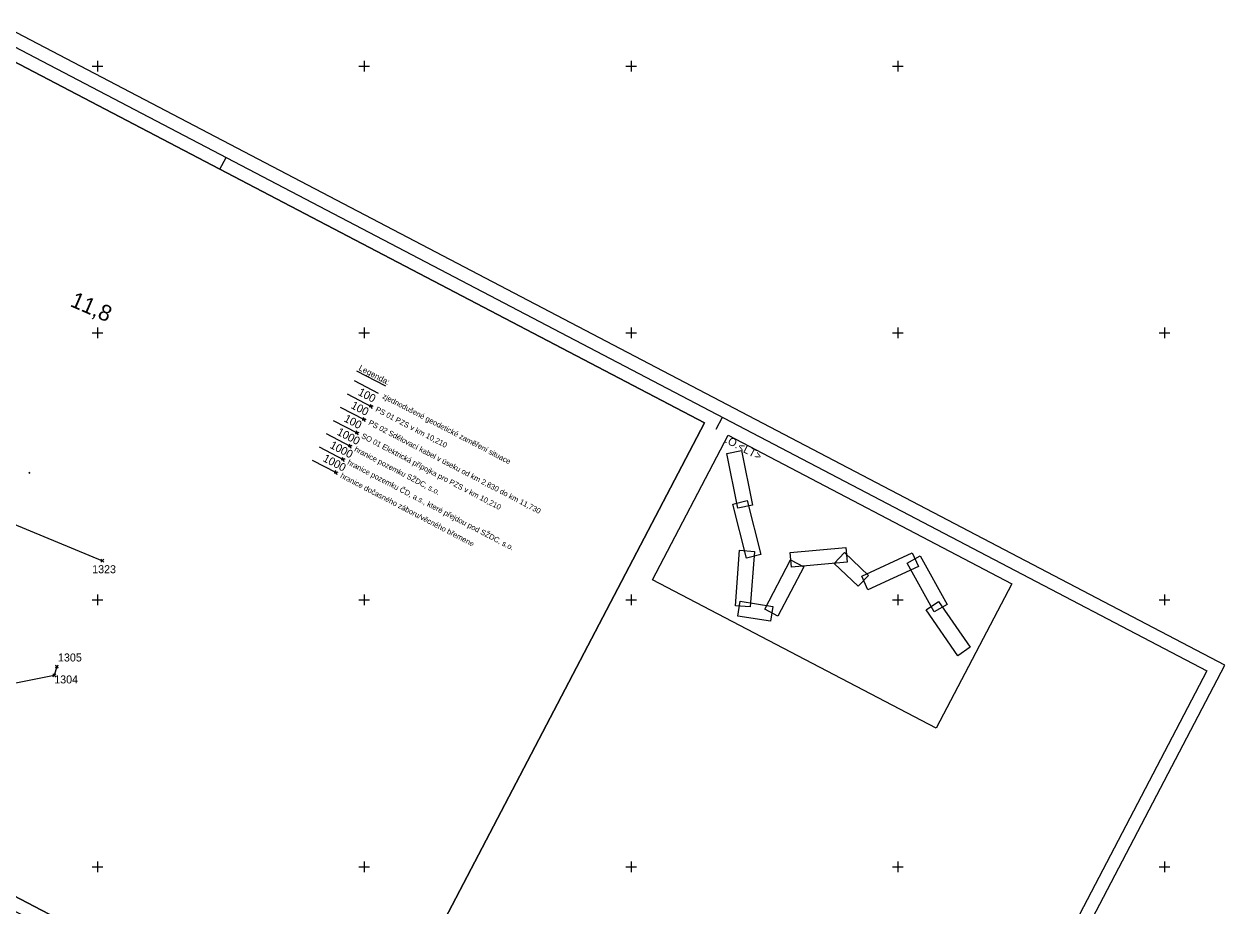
# Model space of a CAD drawing. Extents: x -866402 to -860377, y -1041908 to -1038598.
# Drawn here: x -860827.5 to -860377.4, y -1040314.7 to -1039984.3 of the extents above; entities that cross this region are included whole.
import ezdxf

# ---------------------------------------------------------------- set-up
doc = ezdxf.new("R2010")
doc.units = 0
for name, color, linetype in [('DZ_ostat', 7, 'Continuous'), ('SZDC', 7, 'Continuous'), ('VB', 7, 'Continuous'), ('Vrstva 1', 7, 'Continuous'), ('Vrstva 21', 7, 'Continuous'), ('Vrstva 49', 7, 'Continuous'), ('Vrstva 5', 7, 'Continuous'), ('Vrstva 53', 7, 'Continuous'), ('Vrstva 60', 7, 'Continuous'), ('Vrstva 7', 7, 'Continuous')]:
    doc.layers.add(name, color=color, linetype=linetype)

msp = doc.modelspace()

# ---------------------------------------------------------------- linework, layer by layer
at = {"layer": 'DZ_ostat'}
msp.add_line((-860719.53, -1040147.65), (-860710.55, -1040152.34), dxfattribs=at)
at = {"layer": 'SZDC'}
for points in [[(-861261.75, -1039976.4), (-861207.66, -1040016.44), (-861178.07, -1040032.92), (-861123.93, -1040056.86), (-861120.81, -1040053.41), (-861111.29, -1040057.53), (-861106.75, -1040059.49), (-861091.91, -1040065.91), (-861080.02, -1040037.82), (-861096.96, -1040029.84), (-861063.4, -1040039.15), (-861045.83, -1040048.83), (-861015.69, -1040065.42), (-860995.26, -1040081.93), (-860925.73, -1040118.15), (-860902.64, -1040130.18), (-860914.76, -1040137.1), (-860798.14, -1040185.35)], [(-860815.23, -1040225.02), (-860816.21, -1040228.33), (-860833.14, -1040231.75)]]:
    msp.add_lwpolyline(points, dxfattribs=at)
at = {"layer": 'VB'}
msp.add_line((-860719.53, -1040147.65), (-860710.55, -1040152.34), dxfattribs=at)
at = {"layer": 'Vrstva 1'}
for p, q in [((-860754.12, -1040038.65), (-860751.8, -1040034.23)), ((-860568.05, -1040136.01), (-860565.74, -1040131.59))]:
    msp.add_line(p, q, dxfattribs=at)
for points in [[(-861631.44, -1039903.51), (-860515.05, -1040487.66), (-860377.36, -1040224.52), (-861493.75, -1039640.37)], [(-861491.64, -1039647.11), (-860384.11, -1040226.63), (-860517.16, -1040480.91), (-861624.69, -1039901.4)], [(-861617.95, -1039899.29), (-860700.91, -1040379.13), (-860572.48, -1040133.7), (-861489.53, -1039653.85)], [(-861489.53, -1039653.85), (-860572.48, -1040133.7), (-860700.91, -1040379.13), (-861617.95, -1039899.29)]]:
    msp.add_lwpolyline(points, close=True, dxfattribs=at)
at = {"layer": 'Vrstva 21'}
for points in [[(-860591.95, -1040192.47), (-860563.63, -1040138.33), (-860457.3, -1040193.96), (-860485.63, -1040248.1)], [(-860564.09, -1040145.2), (-860558.62, -1040144.08), (-860554.46, -1040164.51), (-860559.93, -1040165.62)], [(-860564.09, -1040145.2), (-860558.62, -1040144.08), (-860554.46, -1040164.51), (-860559.93, -1040165.62)], [(-860561.83, -1040164.17), (-860556.41, -1040162.81), (-860551.35, -1040183.03), (-860556.76, -1040184.39)], [(-860559.34, -1040181.46), (-860553.77, -1040181.87), (-860555.31, -1040202.66), (-860560.88, -1040202.25)], [(-860539.79, -1040187.81), (-860540.29, -1040182.26), (-860519.53, -1040180.39), (-860519.03, -1040185.94)], [(-860523.86, -1040186.34), (-860520.02, -1040182.29), (-860511.04, -1040190.83), (-860514.89, -1040194.87)], [(-860511.19, -1040196.24), (-860513.54, -1040191.18), (-860494.63, -1040182.41), (-860492.28, -1040187.47)], [(-860496.52, -1040186.29), (-860491.66, -1040183.56), (-860481.44, -1040201.73), (-860486.31, -1040204.46)], [(-860544.93, -1040206.14), (-860549.87, -1040203.55), (-860540.21, -1040185.08), (-860535.26, -1040187.66)], [(-860559.97, -1040206.07), (-860559.08, -1040200.56), (-860546.85, -1040202.54), (-860547.74, -1040208.05)], [(-860489.35, -1040203.8), (-860484.77, -1040200.62), (-860472.88, -1040217.75), (-860477.47, -1040220.93)]]:
    msp.add_lwpolyline(points, close=True, dxfattribs=at)
at = {"layer": 'Vrstva 49'}
for p, q in [((-860825.86, -1040152.31), (-860825.39, -1040152.49)), ((-860825.53, -1040152.17), (-860825.72, -1040152.63))]:
    msp.add_line(p, q, dxfattribs=at)
at = {"layer": 'Vrstva 5'}
for p, q in [((-860800, -1039998), (-860800, -1040002)), ((-860700, -1039998), (-860700, -1040002)), ((-860600, -1039998), (-860600, -1040002)), ((-860500, -1039998), (-860500, -1040002)), ((-860802, -1040000), (-860798, -1040000)), ((-860702, -1040000), (-860698, -1040000)), ((-860602, -1040000), (-860598, -1040000)), ((-860502, -1040000), (-860498, -1040000)), ((-860800, -1040098), (-860800, -1040102)), ((-860700, -1040098), (-860700, -1040102)), ((-860600, -1040098), (-860600, -1040102)), ((-860500, -1040098), (-860500, -1040102)), ((-860400, -1040098), (-860400, -1040102)), ((-860802, -1040100), (-860798, -1040100)), ((-860702, -1040100), (-860698, -1040100)), ((-860602, -1040100), (-860598, -1040100)), ((-860502, -1040100), (-860498, -1040100)), ((-860402, -1040100), (-860398, -1040100)), ((-860802, -1040200), (-860798, -1040200)), ((-860800, -1040198), (-860800, -1040202)), ((-860702, -1040200), (-860698, -1040200)), ((-860700, -1040198), (-860700, -1040202)), ((-860602, -1040200), (-860598, -1040200)), ((-860600, -1040198), (-860600, -1040202)), ((-860502, -1040200), (-860498, -1040200)), ((-860500, -1040198), (-860500, -1040202)), ((-860402, -1040200), (-860398, -1040200)), ((-860400, -1040198), (-860400, -1040202)), ((-860802, -1040300), (-860798, -1040300)), ((-860800, -1040298), (-860800, -1040302)), ((-860702, -1040300), (-860698, -1040300)), ((-860700, -1040298), (-860700, -1040302)), ((-860602, -1040300), (-860598, -1040300)), ((-860600, -1040298), (-860600, -1040302)), ((-860502, -1040300), (-860498, -1040300)), ((-860500, -1040298), (-860500, -1040302)), ((-860402, -1040300), (-860398, -1040300)), ((-860400, -1040298), (-860400, -1040302))]:
    msp.add_line(p, q, dxfattribs=at)
at = {"layer": 'Vrstva 53'}
for p, q in [((-860714.27, -1040137.73), (-860705.29, -1040142.42)), ((-860716.9, -1040142.69), (-860707.92, -1040147.38))]:
    msp.add_line(p, q, dxfattribs=at)
at = {"layer": 'Vrstva 60'}
for p, q in [((-860696.8, -1040127.34), (-860698.15, -1040127.77)), ((-860698.01, -1040127.72), (-860696.66, -1040127.3)), ((-860697.21, -1040128.14), (-860697.64, -1040126.79)), ((-860697.59, -1040126.93), (-860697.17, -1040128.28)), ((-860697.4, -1040127.53), (-860697.4, -1040127.53)), ((-860699.43, -1040132.31), (-860700.78, -1040132.73)), ((-860700.64, -1040132.69), (-860699.29, -1040132.26)), ((-860699.84, -1040133.1), (-860700.27, -1040131.75)), ((-860700.22, -1040131.89), (-860699.8, -1040133.24)), ((-860700.03, -1040132.5), (-860700.03, -1040132.5)), ((-860702.06, -1040137.27), (-860703.41, -1040137.69)), ((-860703.27, -1040137.65), (-860701.92, -1040137.23)), ((-860702.47, -1040138.07), (-860702.9, -1040136.72)), ((-860702.85, -1040136.85), (-860702.43, -1040138.2)), ((-860702.66, -1040137.46), (-860702.66, -1040137.46)), ((-860704.69, -1040142.23), (-860706.04, -1040142.65)), ((-860705.9, -1040142.61), (-860704.55, -1040142.19)), ((-860705.1, -1040143.03), (-860705.53, -1040141.68)), ((-860705.48, -1040141.81), (-860705.06, -1040143.16)), ((-860705.29, -1040142.42), (-860705.29, -1040142.42)), ((-860707.32, -1040147.19), (-860708.67, -1040147.61)), ((-860708.53, -1040147.57), (-860707.18, -1040147.15)), ((-860707.73, -1040147.99), (-860708.16, -1040146.64)), ((-860708.11, -1040146.77), (-860707.69, -1040148.12)), ((-860707.92, -1040147.38), (-860707.92, -1040147.38)), ((-860709.95, -1040152.15), (-860711.3, -1040152.58)), ((-860711.16, -1040152.53), (-860709.81, -1040152.11)), ((-860710.36, -1040152.95), (-860710.79, -1040151.6)), ((-860710.74, -1040151.74), (-860710.32, -1040153.09)), ((-860710.55, -1040152.34), (-860710.55, -1040152.34)), ((-860797.69, -1040185.8), (-860798.69, -1040184.8)), ((-860797.69, -1040184.9), (-860798.69, -1040185.9)), ((-860798.59, -1040185.8), (-860797.59, -1040184.8)), ((-860798.59, -1040184.9), (-860797.59, -1040185.9)), ((-860798.14, -1040185.35), (-860798.14, -1040185.35)), ((-860814.78, -1040225.47), (-860815.78, -1040224.47)), ((-860814.78, -1040224.57), (-860815.78, -1040225.57)), ((-860815.68, -1040225.47), (-860814.68, -1040224.47)), ((-860815.68, -1040224.57), (-860814.68, -1040225.57)), ((-860815.76, -1040228.78), (-860816.76, -1040227.78)), ((-860815.76, -1040227.88), (-860816.76, -1040228.88)), ((-860816.66, -1040228.78), (-860815.66, -1040227.78)), ((-860816.66, -1040227.88), (-860815.66, -1040228.88)), ((-860816.21, -1040228.33), (-860816.21, -1040228.33)), ((-860815.23, -1040225.02), (-860815.23, -1040225.02))]:
    msp.add_line(p, q, dxfattribs=at)
at = {"layer": 'Vrstva 7'}
for p, q in [((-860702.87, -1040114.15), (-860692.02, -1040119.83)), ((-860703.75, -1040117.88), (-860694.77, -1040122.57)), ((-860706.38, -1040122.84), (-860697.4, -1040127.53)), ((-860709.01, -1040127.8), (-860700.03, -1040132.5)), ((-860711.64, -1040132.76), (-860702.66, -1040137.46))]:
    msp.add_line(p, q, dxfattribs=at)

# ---------------------------------------------------------------- texts
at = {"layer": 'Vrstva 1'}
msp.add_text('.O.<LT>', height=3, rotation=332.3792, dxfattribs=at).set_placement((-860565.02, -1040140.99))
at = {"layer": 'Vrstva 60'}
for s, p in [('100', (-860702.62, -1040123.1)), ('100', (-860705.25, -1040128.06)), ('100', (-860707.88, -1040133.03)), ('1000', (-860710.51, -1040137.99)), ('1000', (-860713.14, -1040142.95)), ('1000', (-860715.77, -1040147.91))]:
    msp.add_text(s, height=3, rotation=332.3792, dxfattribs=at).set_placement(p)
for s, p in [('1323', (-860801.99, -1040190.04)), ('1305', (-860814.8, -1040223.11)), ('1304', (-860816.21, -1040231.33))]:
    msp.add_text(s, height=3, dxfattribs=at).set_placement(p)
at = {"layer": 'Vrstva 7'}
for s, height, rotation, p in [('11,8', 6, 336.6026, (-860810.59, -1040089.87)), ('Legenda:', 2.25, 332.3792, (-860702.31, -1040113.81)), ('zjednodušené geodetické zaměření situace', 2.025, 332.3792, (-860693.39, -1040124.35)), ('PS 01 PZS v km 10,210', 2.025, 332.3792, (-860696.02, -1040129.31)), ('PS 02 Sdělovací kabel v úseku od km 2,830 do km 11,730', 2.025, 332.3792, (-860698.65, -1040134.28)), ('SO 01 Elektrická přípojka pro PZS v km 10,210', 2.025, 332.3792, (-860701.28, -1040139.24)), ('hranice pozemku SŽDC, s.o.', 2.025, 332.3792, (-860703.91, -1040144.2)), ('hranice pozemku ČD, a.s., které přejdou pod SŽDC, s.o.', 2.025, 332.3792, (-860706.54, -1040149.16)), ('hranice dočasného záboru/věcného břemene', 2.025, 332.3792, (-860709.17, -1040154.12))]:
    msp.add_text(s, height=height, rotation=rotation, dxfattribs=at).set_placement(p)

doc.saveas('drawing.dxf')
